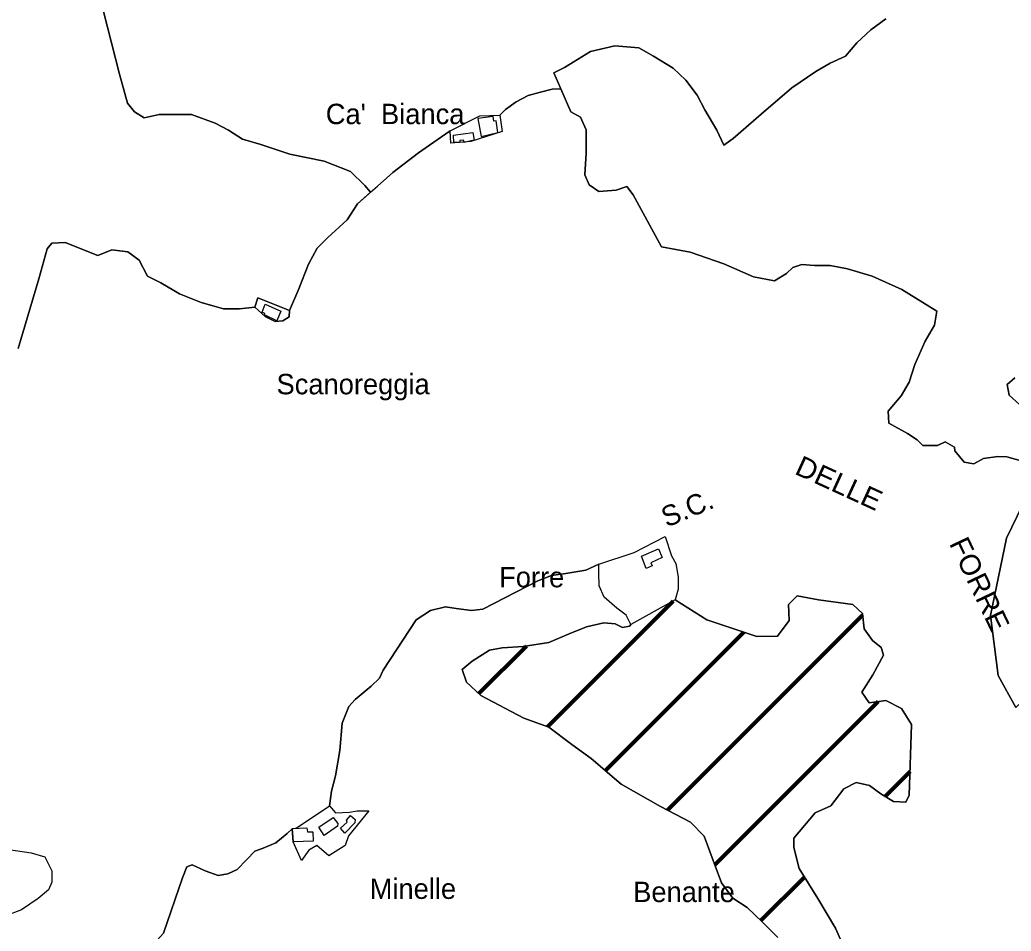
# Model space of a CAD drawing. Extents: x 645880 to 658994, y 884400 to 894744.
# Drawn here: x 656523 to 657349, y 892496 to 893255 of the extents above; entities that cross this region are included whole.
import ezdxf
from ezdxf.enums import TextEntityAlignment as Align

# ---------------------------------------------------------------- set-up
doc = ezdxf.new("R2010")
doc.units = 0
doc.header["$LTSCALE"] = 10
for name, color, linetype, lineweight in [('16', 7, 'Continuous', 25), ('17', 7, 'Continuous', 25), ('18', 7, 'Continuous', 25), ('2', 7, 'Continuous', 25), ('4', 7, 'Continuous', 25)]:
    doc.layers.add(name, color=color, linetype=linetype, lineweight=lineweight)
doc.layers.add('60', color=7, linetype='Continuous')

msp = doc.modelspace()

# ---------------------------------------------------------------- linework, layer by layer
at = {"layer": '16'}
msp.add_line((657353.04, 892682.28), (657338.35, 892708.74), dxfattribs=at)
for points in [[(656592.99, 893262.26), (656606.17, 893210.23), (656612.76, 893186.04), (656618.62, 893178.71), (656626.68, 893173.58), (656639.13, 893176.51), (656653.78, 893176.51), (656666.23, 893176.51), (656686.01, 893169.19)], [(656686.01, 893169.19), (656666.23, 893176.51), (656653.78, 893176.51), (656639.13, 893176.51), (656626.68, 893173.58), (656618.62, 893178.71), (656612.76, 893186.04), (656606.17, 893210.23), (656592.99, 893262.26)], [(656923.22, 893176.04), (656927.85, 893180.74), (656936.83, 893186.98), (656946.81, 893192.22), (656957.04, 893194.97), (656966.77, 893197.46), (656973.96, 893197.95), (656968.16, 893211.13), (656977.14, 893215.74), (656998.8, 893229.07), (657019.01, 893233.76), (657039.1, 893232.08), (657051.09, 893224.97), (657067.46, 893215.23), (657078.03, 893204.98), (657087.54, 893192.69), (657093.87, 893180.39), (657104.06, 893163.39), (657109.76, 893150.99), (657117.46, 893156.35), (657140.9, 893176.79), (657166.35, 893198.57), (657186.44, 893212.31), (657198.46, 893219.33), (657211.14, 893224.97), (657220.64, 893236.24), (657232.31, 893247.17), (657244.7, 893256.22)], [(656973.96, 893197.95), (656966.77, 893197.46), (656957.04, 893194.97), (656946.81, 893192.22), (656936.83, 893186.98), (656927.85, 893180.74), (656923.22, 893176.04), (656925.14, 893162.31), (656898.85, 893154), (656895.89, 893153.75)], [(656973.96, 893197.95), (656966.77, 893197.46), (656957.04, 893194.97), (656946.81, 893192.22), (656936.83, 893186.98), (656927.85, 893180.74), (656923.22, 893176.04)], [(657029, 893116.33), (657020.13, 893113.37), (657005.67, 893112.38), (656997.49, 893117.96), (656993.87, 893126.18), (656995.19, 893144.27), (656995.19, 893163.68), (656990.26, 893174.21), (656982.37, 893178.81), (656973.96, 893197.95)], [(656686.01, 893169.19), (656697, 893163.32), (656708.72, 893155.99), (656724.1, 893151.6), (656748.27, 893143.54), (656776.83, 893137.67), (656798.81, 893128.88), (656810.53, 893117.15), (656815.29, 893111.7)], [(656815.29, 893111.7), (656810.53, 893117.15), (656798.81, 893128.88), (656776.83, 893137.67), (656748.27, 893143.54), (656724.1, 893151.6), (656708.72, 893155.99), (656697, 893163.32), (656686.01, 893169.19)], [(656815.29, 893111.7), (656821.07, 893116.83), (656834.05, 893128.06), (656855.24, 893144.54), (656870.96, 893155.28), (656881.87, 893162.99), (656906.51, 893175.49), (656923.22, 893176.04)], [(656881.87, 893162.99), (656870.96, 893155.28), (656855.24, 893144.54), (656834.05, 893128.06), (656821.07, 893116.83), (656804.49, 893102.1), (656796, 893088.62), (656779.54, 893073.64), (656771.05, 893065.15), (656763.57, 893051.67), (656755.59, 893031.2), (656747.99, 893012.95), (656747.53, 893007.88), (656742.22, 893004.42), (656736, 893003.96), (656727.47, 893008.11), (656719.11, 893015.92)], [(656889.92, 893153.25), (656889.93, 893153.09), (656888.03, 893153.09), (656882.26, 893152.61), (656881.87, 893162.99)], [(656895.89, 893153.75), (656893.4, 893153.19), (656893.3, 893153.53), (656889.92, 893153.25)], [(656747.99, 893012.95), (656755.59, 893031.2), (656763.57, 893051.67), (656771.05, 893065.15), (656779.54, 893073.64), (656796, 893088.62), (656804.49, 893102.1), (656815.29, 893111.7)], [(657359.38, 892887.18), (657345.49, 892890.99), (657338.12, 892891.33), (657326.07, 892889.65), (657318.03, 892885.29), (657310, 892886.63), (657302.22, 892896.06), (657301.96, 892899.03), (657294.26, 892903.72), (657287.76, 892900.67), (657275.61, 892900.67), (657270.82, 892905.4), (657262.78, 892910.43), (657247.38, 892919.14), (657246.71, 892929.19), (657257.45, 892941.96), (657264.32, 892953.23), (657269.07, 892968.09), (657277.52, 892987.56), (657285.44, 893000.89), (657287.19, 893012.59), (657258.14, 893030.52), (657233.31, 893041.8), (657212.71, 893047.95), (657198.45, 893050.51), (657185.25, 893050.51), (657174.68, 893051.53), (657167.29, 893048.97), (657162, 893043.85), (657151.97, 893037.7), (657134.54, 893041.28), (657109.71, 893052.04), (657081.72, 893061.78), (657057.87, 893066.04), (657034.26, 893109.42), (657029, 893116.33)], [(656719.11, 893015.92), (656706.18, 893014.36), (656692.89, 893014.36), (656685.08, 893016.71), (656674.14, 893019.84), (656656.17, 893026.87), (656640.54, 893036.26), (656629.6, 893041.73), (656622.57, 893055.02), (656613.19, 893062.06), (656599.91, 893063.62), (656588.19, 893058.93), (656560.84, 893069.87), (656549.9, 893069.09), (656545.99, 893064.4), (656538.96, 893039.38), (656521.77, 892981.53)], [(656521.77, 892981.53), (656538.96, 893039.38), (656545.99, 893064.4), (656549.9, 893069.09), (656560.84, 893069.87), (656588.19, 893058.93), (656599.91, 893063.62), (656613.19, 893062.06), (656622.57, 893055.02), (656629.6, 893041.73), (656640.54, 893036.26), (656656.17, 893026.87), (656674.14, 893019.84), (656685.08, 893016.71), (656692.89, 893014.36), (656706.18, 893014.36), (656719.11, 893015.92), (656721.45, 893023.52), (656747.99, 893012.95)], [(657338.35, 892708.74), (657332.09, 892758.81), (657345.47, 892823.2), (657372.2, 892878.95)], [(656781.1, 892600.18), (656782.86, 892612.26), (656786.32, 892625.12), (656789.78, 892646.39), (656791.76, 892669.14), (656797.2, 892682.99), (656802.64, 892688.92), (656815.98, 892699.8), (656822.9, 892706.73), (656825.87, 892713.16), (656853.55, 892755.2), (656865.41, 892763.11), (656877.77, 892766.08), (656886.67, 892764.59), (656899.52, 892763.11), (656908.91, 892764.1), (656954.88, 892787.84), (656966.25, 892792.29), (656978.12, 892793.77), (656994.92, 892796.74), (657005.73, 892801.5), (657035.01, 892811.42), (657060.83, 892824.81), (657066.08, 892808.58), (657069.82, 892802.12), (657071.86, 892790.9), (657071.86, 892780.71), (657069.29, 892771.77), (657095.63, 892755.24), (657137.33, 892741.42), (657154.41, 892741.67), (657164.21, 892754.74), (657163.71, 892768.07), (657170.99, 892775.11), (657188.58, 892771.84), (657217.22, 892768.07), (657225.26, 892760.52), (657226.68, 892747.75), (657233.66, 892738.07), (657240.83, 892732.12)], [(657005.73, 892801.5), (656994.92, 892796.74), (656978.12, 892793.77), (656966.25, 892792.29), (656954.88, 892787.84), (656908.91, 892764.1), (656899.52, 892763.11), (656886.67, 892764.59), (656877.77, 892766.08), (656865.41, 892763.11), (656853.55, 892755.2), (656825.87, 892713.16), (656822.9, 892706.73), (656815.98, 892699.8), (656802.64, 892688.92), (656797.2, 892682.99), (656791.76, 892669.14), (656789.78, 892646.39), (656786.32, 892625.12), (656782.86, 892612.26), (656781.1, 892600.18), (656786.3, 892594.24), (656797.8, 892594.9), (656804.37, 892595.89), (656814.06, 892596.09), (656796.97, 892575.04), (656794.34, 892567.14), (656780.55, 892558.59), (656770.76, 892566.97), (656763.84, 892563.28), (656757.85, 892554.51), (656750.93, 892570.2), (656750.1, 892581.12)], [(657129.27, 892515.45), (657117.3, 892523.19), (657107.95, 892536.12), (657100.97, 892554.5), (657093.49, 892574.83), (657082.01, 892586.44), (657057.08, 892599.5), (657024.16, 892618.37), (656999.22, 892639.66), (656983.1, 892651.29), (656964.02, 892665.74), (656943.04, 892673.38), (656907.35, 892692.19), (656895.36, 892703.37), (656891.82, 892713.73), (656899.99, 892720.82), (656914.51, 892730.04), (656924.99, 892731.97), (656942.44, 892732.94), (656963.89, 892736.33), (656980.85, 892743.59), (656995.31, 892749.39), (657009.78, 892752.78), (657019.25, 892751.81), (657025.24, 892748.91), (657031.22, 892749.88), (657032.39, 892751.27), (657028.29, 892759.07), (657020.69, 892765.07), (657010.09, 892774.07), (657005.89, 892783.47), (657005.5, 892794.35), (657005.73, 892801.5)], [(657240.83, 892732.12), (657242.85, 892725.77), (657233.87, 892709.31), (657224.9, 892694.8), (657230.88, 892686.09), (657244.85, 892688.03), (657257.81, 892681.25), (657266.18, 892667.96), (657264.36, 892609.19), (657261.44, 892603.15), (657251.14, 892603.65), (657240.59, 892610.19), (657231.04, 892617.23), (657219.99, 892619.49), (657209.69, 892614.21), (657198.95, 892600.21), (657185.98, 892594.4), (657168.24, 892573.24), (657167.99, 892565.45), (657172.52, 892547.85), (657188.09, 892522.96), (657202.91, 892498.07), (657208.19, 892486.26)], [(656609.9, 892467.27), (656608.38, 892481.69), (656620.24, 892479.21), (656632.6, 892482.68), (656642.98, 892494.05), (656658.8, 892540.05), (656662.26, 892549.44), (656666.71, 892550.93), (656677.58, 892545.98), (656688.46, 892542.03), (656696.37, 892543.51), (656704.27, 892546.97), (656712.18, 892555.38), (656719.1, 892562.3), (656726.02, 892564.78), (656736.4, 892569.23), (656745.8, 892577.14), (656750.1, 892581.12), (656753.6, 892581.81), (656770.09, 892592.62), (656781.1, 892600.18)], [(656750.1, 892581.12), (656745.8, 892577.14), (656736.4, 892569.23), (656726.02, 892564.78), (656719.1, 892562.3), (656712.18, 892555.38), (656704.27, 892546.97), (656696.37, 892543.51), (656688.46, 892542.03), (656677.58, 892545.98), (656666.71, 892550.93), (656662.26, 892549.44), (656658.8, 892540.05), (656642.98, 892494.05), (656632.6, 892482.68), (656620.24, 892479.21), (656608.38, 892481.69), (656609.9, 892467.27), (656616.63, 892464.81), (656631.08, 892459.55), (656631.35, 892452.76), (656623.62, 892440.56), (656623.85, 892433.23), (656626.48, 892425.34)], [(656512.07, 892564.06), (656532.7, 892561.06), (656544.04, 892557.56), (656549.71, 892546.06), (656549.71, 892536.55), (656547.13, 892530.05), (656538.37, 892523.05), (656524.45, 892513.55), (656511.56, 892508.55)], [(657154.7, 892490.29), (657141.74, 892503.36), (657129.27, 892515.45)]]:
    msp.add_lwpolyline(points, dxfattribs=at)
at = {"layer": '17'}
for points in [[(657352.29, 892956.84), (657345.94, 892951.51), (657347.65, 892942.45), (657356.22, 892934.85)], [(657372.2, 892878.95), (657345.47, 892823.2)], [(657345.47, 892823.2), (657332.09, 892758.81), (657338.35, 892708.74), (657353.04, 892682.28), (657368.46, 892696.73), (657432.23, 892699.3), (657420.85, 892670.28), (657416.14, 892641.66), (657432.69, 892620.86), (657421.93, 892611.12), (657431.09, 892593.64), (657436.11, 892576.78), (657435.9, 892563.89), (657431.67, 892548.82), (657425.58, 892537.82), (657419.66, 892527.66)]]:
    msp.add_lwpolyline(points, dxfattribs=at)
at = {"layer": '18', "lineweight": 120}
for p, q in [((656962.89, 892666.15), (657067.52, 892770.79)), ((657062.9, 892596.45), (657225.43, 892758.99)), ((657011.1, 892629.51), (657126.57, 892744.98)), ((656905.66, 892693.77), (656945.27, 892733.39)), ((657102.3, 892551), (657238.43, 892687.14)), ((657244.14, 892607.99), (657264.97, 892628.82)), ((657140.61, 892504.46), (657176.94, 892540.79))]:
    msp.add_line(p, q, dxfattribs=at)
at = {"layer": '18'}
for points in [[(657244.7, 893256.22), (657232.31, 893247.17), (657220.64, 893236.24), (657211.14, 893224.97), (657198.46, 893219.33), (657186.44, 893212.31), (657166.35, 893198.57), (657140.9, 893176.79), (657117.46, 893156.35), (657109.76, 893150.99), (657104.06, 893163.39), (657093.87, 893180.39), (657087.54, 893192.69), (657078.03, 893204.98), (657067.46, 893215.23), (657051.09, 893224.97), (657039.1, 893232.08), (657019.01, 893233.76), (656998.8, 893229.07), (656977.14, 893215.74), (656968.16, 893211.13), (656982.37, 893178.81), (656990.26, 893174.21), (656995.19, 893163.68), (656995.19, 893144.27), (656993.87, 893126.18), (656997.49, 893117.96), (657005.67, 893112.38), (657020.13, 893113.37)], [(657020.13, 893113.37), (657029, 893116.33), (657034.26, 893109.42), (657057.87, 893066.04), (657081.72, 893061.78), (657109.71, 893052.04), (657134.54, 893041.28), (657151.97, 893037.7), (657162, 893043.85), (657167.29, 893048.97), (657174.68, 893051.53), (657185.25, 893050.51), (657198.45, 893050.51), (657212.71, 893047.95), (657233.31, 893041.8), (657258.14, 893030.52), (657287.19, 893012.59), (657285.44, 893000.89), (657277.52, 892987.56), (657269.07, 892968.09), (657264.32, 892953.23), (657257.45, 892941.96), (657246.71, 892929.19), (657247.38, 892919.14), (657262.78, 892910.43), (657270.82, 892905.4), (657275.61, 892900.67), (657287.76, 892900.67), (657294.26, 892903.72), (657301.96, 892899.03), (657302.22, 892896.06), (657310, 892886.63), (657318.03, 892885.29), (657326.07, 892889.65), (657338.12, 892891.33), (657345.49, 892890.99), (657359.38, 892887.18)], [(657356.22, 892934.85), (657347.65, 892942.45), (657345.94, 892951.51), (657352.29, 892956.84)], [(657185.98, 892594.4), (657198.95, 892600.21), (657209.69, 892614.21), (657219.99, 892619.49), (657231.04, 892617.23), (657240.59, 892610.19), (657251.14, 892603.65), (657261.44, 892603.15), (657264.36, 892609.19), (657266.18, 892667.96), (657257.81, 892681.25), (657244.85, 892688.03), (657230.88, 892686.09), (657224.9, 892694.8), (657233.87, 892709.31), (657242.85, 892725.77), (657240.83, 892732.12), (657233.66, 892738.07), (657226.68, 892747.75), (657225.26, 892760.52), (657217.22, 892768.07), (657188.58, 892771.84), (657170.99, 892775.11), (657163.71, 892768.07), (657164.21, 892754.74), (657154.41, 892741.67), (657137.33, 892741.42), (657095.63, 892755.24), (657069.29, 892771.77), (657032.39, 892751.27), (657031.22, 892749.88), (657025.24, 892748.91), (657019.25, 892751.81), (657009.78, 892752.78), (656995.31, 892749.39), (656980.85, 892743.59), (656963.89, 892736.33), (656942.44, 892732.94), (656924.99, 892731.97), (656914.51, 892730.04)], [(656914.51, 892730.04), (656899.99, 892720.82), (656891.82, 892713.73), (656895.36, 892703.37), (656907.35, 892692.19), (656943.04, 892673.38), (656964.02, 892665.74), (656983.1, 892651.29), (656999.22, 892639.66), (657024.16, 892618.37), (657057.08, 892599.5), (657082.01, 892586.44), (657093.49, 892574.83), (657100.97, 892554.5), (657107.95, 892536.12), (657117.3, 892523.19), (657129.27, 892515.45), (657141.74, 892503.36), (657154.7, 892490.29)], [(657359.44, 892324.61), (657337.24, 892330.92), (657307.55, 892346.59), (657268, 892369.95), (657243.11, 892387.21), (657224.52, 892410.84), (657212.97, 892428.69), (657206.94, 892441.76), (657205.18, 892455.84), (657207.19, 892466.9), (657208.69, 892477.46), (657208.19, 892486.26), (657202.91, 892498.07), (657188.09, 892522.96), (657172.52, 892547.85), (657167.99, 892565.45), (657168.24, 892573.24), (657185.98, 892594.4)], [(656512.07, 892564.06), (656532.7, 892561.06), (656544.04, 892557.56), (656549.71, 892546.06), (656549.71, 892536.55), (656547.13, 892530.05), (656538.37, 892523.05), (656524.45, 892513.55), (656511.56, 892508.55)]]:
    msp.add_lwpolyline(points, dxfattribs=at)
at = {"layer": '2'}
for points in [[(656794.34, 892567.14), (656780.55, 892558.59), (656770.76, 892566.97), (656763.84, 892563.28), (656757.85, 892554.51), (656750.93, 892570.2), (656750.1, 892581.12), (656753.6, 892581.81), (656770.09, 892592.62), (656781.1, 892600.18), (656786.3, 892594.24), (656797.8, 892594.9), (656804.37, 892595.89), (656814.06, 892596.09), (656796.97, 892575.04)], [(656772.34, 892582.51), (656784.14, 892590.53), (656788.07, 892585.58), (656787.93, 892583.1), (656776.71, 892575.52)], [(656790.38, 892581.56), (656795.99, 892586.55), (656795.37, 892588.27), (656798.8, 892592.01), (656802.55, 892588.73), (656802.23, 892585.93), (656793.97, 892577.5)], [(656750.1, 892581.18), (656762.29, 892581.79), (656762.73, 892578.43), (656767.39, 892578.58), (656767.68, 892570.71), (656750.9, 892570.18), (656750.1, 892581.12), (656750.93, 892570.2)]]:
    msp.add_lwpolyline(points, close=True, dxfattribs=at)
at = {"layer": '4'}
for points in [[(656925.14, 893162.31), (656898.85, 893154), (656882.26, 893152.61), (656881.87, 893162.99), (656906.51, 893175.49), (656923.22, 893176.04)], [(656904.79, 893173.08), (656907.61, 893158.1), (656921.5, 893161.48), (656919.97, 893171.09), (656918.27, 893171.05), (656917.52, 893174.9)], [(656884.62, 893159.33), (656900.76, 893161.33), (656901.88, 893155.09), (656893.4, 893153.19), (656892.79, 893155.14), (656889.83, 893154.73), (656889.93, 893153.09), (656884.92, 893153.09)], [(656727.47, 893008.11), (656736, 893003.96), (656742.22, 893004.42), (656747.53, 893007.88), (656747.99, 893012.95), (656721.45, 893023.52), (656719.11, 893015.92)], [(656725.19, 893011.75), (656727.71, 893018.38), (656740.67, 893012.41), (656737.32, 893004.44), (656726.95, 893009.6), (656727.42, 893010.71)], [(657005.73, 892801.5), (657035.01, 892811.42), (657060.83, 892824.81), (657066.08, 892808.58), (657069.82, 892802.12), (657071.86, 892790.9), (657071.86, 892780.71), (657069.29, 892771.77), (657032.39, 892751.27), (657028.29, 892759.07), (657020.69, 892765.07), (657010.09, 892774.07), (657005.89, 892783.47), (657005.5, 892794.35)], [(657041.11, 892808.25), (657055.24, 892814.51), (657058.48, 892807.06), (657048.98, 892802.85), (657049.96, 892800.15), (657045.1, 892798.1)]]:
    msp.add_lwpolyline(points, close=True, dxfattribs=at)

# ---------------------------------------------------------------- texts
at = {"layer": '60'}
for s, p in [("Ca'  Bianca", (656835.86, 893168.43)), ('Scanoreggia', (656800.88, 892943.22)), ('Forre', (656949.68, 892782.34)), ('Minelle', (656850.68, 892522.58)), ('Benante', (657076.61, 892519.94))]:
    msp.add_text(s, height=17, dxfattribs=at).set_placement(p, align=Align.CENTER)
at = {"layer": '60', "width": 1.05}
for s, rotation, p in [('DELLE', 335.382, (657202.26, 892861.46)), ('FORRE', 295.48, (657315.26, 892781.25))]:
    msp.add_text(s, height=17, rotation=rotation, dxfattribs=at).set_placement(p, align=Align.CENTER)
at = {"layer": '60'}
msp.add_text('S.C.', height=17, rotation=22.657, dxfattribs=at).set_placement((657082.57, 892840.53), align=Align.CENTER)

doc.saveas('drawing.dxf')
